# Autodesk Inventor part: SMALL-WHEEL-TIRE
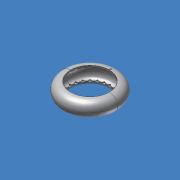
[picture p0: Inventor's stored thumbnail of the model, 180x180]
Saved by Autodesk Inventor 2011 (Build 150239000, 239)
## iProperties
Created: 2007-08
Part Number: SMALL-WHEEL-TIRE
Material: Rubber
Document SubType Name: Modeling
Density: 0.93 g/cm^3
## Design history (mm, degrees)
feature "Base1"
body "Solid1"
